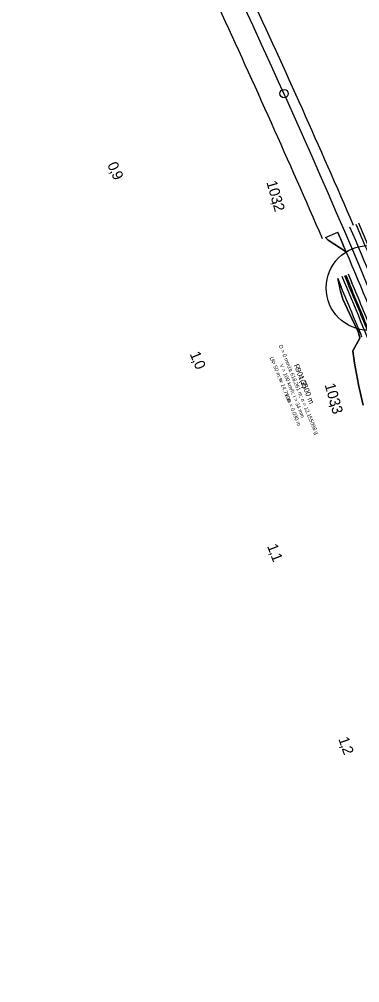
# Model space of a CAD drawing. Extents: x -678487 to -674601, y -1104811 to -1093295.
# Drawn here: x -676479.9 to -676319.1, y -1100215.5 to -1099760.6 of the extents above; entities that cross this region are included whole.
import ezdxf

# ---------------------------------------------------------------- set-up
doc = ezdxf.new("R2010")
doc.units = 0
for name, color, linetype in [('00_MiNGO', 7, 'Continuous'), ('SOxx02xx_Koleje_oblouk_Popis', 7, 'Continuous'), ('SOxx02xx_Staničení_Popis', 7, 'Continuous'), ('SOxx02xx_Staničení_Popis10', 7, 'Continuous'), ('SOxx02xx_ŽSp_hrana', 7, 'Continuous'), ('SOxx02xx_ŽSp_násyp_hrana', 7, 'Continuous'), ('SOxx02xx_ŽSp_násyp_plocha', 7, 'Continuous'), ('SOxx02xx_ŽSp_odvodnění', 7, 'Continuous'), ('SOxx02xx_ŽSp_zářez_hrana', 7, 'Continuous'), ('SOxx02xx_ŽSp_zářez_plocha', 7, 'Continuous'), ('SOxxxxxx_Osa_bod_P', 7, 'Continuous'), ('SOxxxxxx_Staničení_Popis', 7, 'Continuous')]:
    doc.layers.add(name, color=color, linetype=linetype)

msp = doc.modelspace()

# ---------------------------------------------------------------- linework, layer by layer
at = {"layer": '00_MiNGO'}
for centre, radius, start, end in [((-693563.22, -1104838.51), 17994.25, 16.282565, 18.133556), ((-693563.22, -1104838.51), 18010.25, 16.348631, 17.939981), ((-680917.12, -1101849.16), 5008, 23.42836, 24.80346), ((-680917.12, -1101849.16), 4992, 23.42836, 24.80346)]:
    msp.add_arc(centre, radius, start, end, dxfattribs=at)
at = {"layer": 'SOxx02xx_Staničení_Popis'}
msp.add_circle((-676354.85, -1099795.74), 2, dxfattribs=at)
at = {"layer": 'SOxx02xx_Staničení_Popis10'}
msp.add_circle((-676314.96, -1099887.43), 20, dxfattribs=at)
at = {"layer": 'SOxx02xx_ŽSp_hrana'}
for centre, radius, start, end in [((-679543.77, -1101237.56), 3502.82, 21.366, 23.18091), ((-679544.28, -1101237.79), 3497.18, 21.36502, 23.18061)]:
    msp.add_arc(centre, radius, start, end, dxfattribs=at)
at = {"layer": 'SOxx02xx_ŽSp_násyp_hrana'}
for p, q in [((-676335.26, -1099863.72), (-676333.95, -1099864.91)), ((-676333.95, -1099864.91), (-676325.57, -1099870.41))]:
    msp.add_line(p, q, dxfattribs=at)
at = {"layer": 'SOxx02xx_ŽSp_násyp_plocha'}
msp.add_line((-676335.26, -1099863.72), (-676329.43, -1099861.19), dxfattribs=at)
msp.add_lwpolyline([(-676325.47, -1099870.48), (-676333.95, -1099864.91), (-676335.26, -1099863.72)], dxfattribs=at)
msp.add_arc((-679544.28, -1101237.79), 3497.18, 23.01521, 23.18061, dxfattribs=at)
at = {"layer": 'SOxx02xx_ŽSp_odvodnění'}
for p, q in [((-676326.25, -1099881.59), (-676324.51, -1099885.74)), ((-676325.75, -1099881.37), (-676324, -1099885.52))]:
    msp.add_line(p, q, dxfattribs=at)
for centre, radius, start, end in [((-679543.4, -1101237.4), 3506.91, 22.7556, 23.18114), ((-679544.7, -1101237.97), 3492.59, 22.36096, 22.77876), ((-679544.65, -1101237.95), 3493.09, 22.36101, 22.7788)]:
    msp.add_arc(centre, radius, start, end, dxfattribs=at)
at = {"layer": 'SOxx02xx_ŽSp_zářez_hrana'}
for p, q in [((-676324.57, -1099880.87), (-676322.82, -1099885.02)), ((-676327.82, -1099887.15), (-676329.43, -1099882.95)), ((-676328.17, -1099888.92), (-676327.02, -1099892.77)), ((-676327.02, -1099892.77), (-676322.88, -1099901.86)), ((-676322.88, -1099901.86), (-676319.77, -1099908.55)), ((-676319.77, -1099908.55), (-676319.13, -1099911.11)), ((-676319.13, -1099911.11), (-676322.4, -1099917.1)), ((-676322.4, -1099917.1), (-676321.66, -1099922.99)), ((-676321.66, -1099922.99), (-676319.77, -1099933)), ((-676319.77, -1099933), (-676319.71, -1099933.27)), ((-676319.71, -1099933.27), (-676317.54, -1099942.86))]:
    msp.add_line(p, q, dxfattribs=at)
for centre, radius, start, end in [((-679543.5, -1101237.44), 3505.75, 22.7555, 23.18107), ((-679544.8, -1101238.02), 3491.42, 21.36401, 22.85251), ((-679544.99, -1101238.11), 3489.31, 22.3606, 22.77849), ((-679544.54, -1101237.91), 3494.25, 22.36114, 22.77889)]:
    msp.add_arc(centre, radius, start, end, dxfattribs=at)
at = {"layer": 'SOxx02xx_ŽSp_zářez_plocha'}
for p, q in [((-676328.53, -1099887.46), (-676329.43, -1099882.95)), ((-676329.43, -1099882.95), (-676327.82, -1099887.15))]:
    msp.add_line(p, q, dxfattribs=at)
msp.add_lwpolyline([(-676317.54, -1099942.86), (-676319.71, -1099933.27), (-676319.77, -1099933), (-676321.66, -1099922.99), (-676322.4, -1099917.1), (-676319.13, -1099911.11), (-676319.77, -1099908.55), (-676322.88, -1099901.86), (-676327.02, -1099892.77), (-676328.17, -1099888.92), (-676328.53, -1099887.46)], dxfattribs=at)
msp.add_arc((-679544.99, -1101238.11), 3489.31, 22.3606, 22.77849, dxfattribs=at)
at = {"layer": 'SOxxxxxx_Osa_bod_P'}
for centre, radius, start, end in [((-693563.22, -1104838.51), 18002.25, 14.227837, 20.731742), ((-679544.02, -1101237.67), 3500, 17.15654, 27.27761)]:
    msp.add_arc(centre, radius, start, end, dxfattribs=at)
at = {"layer": 'SOxxxxxx_Staničení_Popis'}
msp.add_line((-676354.85, -1099795.74), (-676354.85, -1099795.74), dxfattribs=at)
msp.add_circle((-676354.85, -1099795.74), 2, dxfattribs=at)

# ---------------------------------------------------------------- texts
at = {"layer": 'SOxx02xx_Koleje_oblouk_Popis'}
for s, height, p in [('D = 0 mm; L', 1.8, (-676357.39, -1099914.74)), ('L', 1.8, (-676361.65, -1099920.43)), ('K', 1.8, (-676361.22, -1099921.49)), (' = 50 m; n', 1.8, (-676361.06, -1099921.88)), ('V = 100 km/h; I = 34 mm', 1.8, (-676356.97, -1099923.82)), ('R', 2.5, (-676350.33, -1099923.96)), ('i', 1.8, (-676353.12, -1099925.19)), (' = 618,261 m; α = 12,155098 g', 1.8, (-676353.07, -1099925.32)), ('901(2)', 2.5, (-676349.55, -1099925.87)), ('I', 1.8, (-676357.57, -1099930.42)), (' = 14,7V', 1.8, (-676357.51, -1099930.58)), (' = 3500 m', 2.5, (-676348.61, -1099928.17)), ('100', 1.8, (-676354.58, -1099937.75)), ('; m = 0,030 m', 1.8, (-676354.19, -1099938.71))]:
    msp.add_text(s, height=height, rotation=292.2171, dxfattribs=at).set_placement(p)
at = {"layer": 'SOxx02xx_Staničení_Popis'}
for s, rotation, p in [('0', 294.3294, (-676438.44, -1099829.31)), (',', 294.3294, (-676437.13, -1099832.21)), ('9', 294.3294, (-676436.48, -1099833.66)), ('1', 292.6923, (-676399.47, -1099918.61)), (',', 292.6923, (-676398.25, -1099921.55)), ('0', 292.6923, (-676397.63, -1099923.02)), ('1', 291.0553, (-676362.93, -1100009.35)), (',', 291.0553, (-676361.79, -1100012.32)), ('1', 291.0553, (-676361.22, -1100013.81)), ('1', 289.4183, (-676329.27, -1100100.37)), (',', 289.4183, (-676328.21, -1100103.37)), ('2', 289.4183, (-676327.68, -1100104.87))]:
    msp.add_text(s, height=5, rotation=rotation, dxfattribs=at).set_placement(p)
at = {"layer": 'SOxxxxxx_Staničení_Popis'}
for s, rotation, p in [('0', 294.3294, (-676438.44, -1099829.31)), (',', 294.3294, (-676437.13, -1099832.21)), ('9', 294.3294, (-676436.48, -1099833.66)), ('103', 286.1895, (-676363.24, -1099837.57)), (',', 286.1895, (-676360.58, -1099846.75)), ('2', 286.1895, (-676360.13, -1099848.28)), ('1', 292.6923, (-676399.47, -1099918.61)), (',', 292.6923, (-676398.25, -1099921.55)), ('0', 292.6923, (-676397.63, -1099923.02)), ('103', 285.8712, (-676335.73, -1099933.17)), (',', 285.8712, (-676333.12, -1099942.37)), ('3', 285.8712, (-676332.68, -1099943.9)), ('1', 291.0553, (-676362.93, -1100009.35)), (',', 291.0553, (-676361.79, -1100012.32)), ('1', 291.0553, (-676361.22, -1100013.81)), ('1', 289.4183, (-676329.27, -1100100.37)), (',', 289.4183, (-676328.21, -1100103.37)), ('2', 289.4183, (-676327.68, -1100104.87))]:
    msp.add_text(s, height=5, rotation=rotation, dxfattribs=at).set_placement(p)

doc.saveas('drawing.dxf')
